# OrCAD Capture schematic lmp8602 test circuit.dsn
size A; title: INA293 40-V High-Voltage, High Bandwidth, Unidirectional, 110-V Common-Mode Current-Sense Amplifier; rev: E1; note: SBOS870
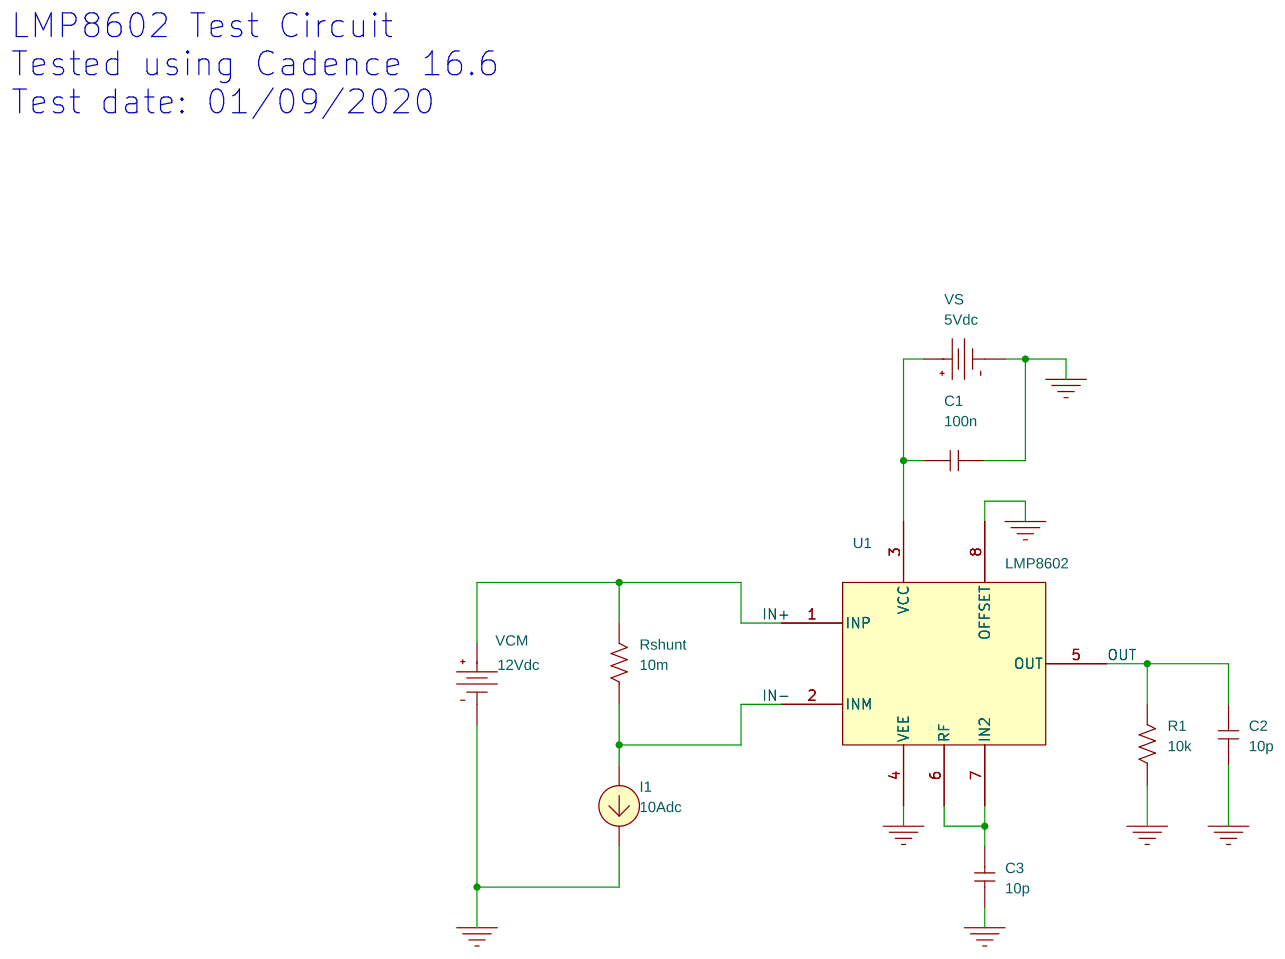
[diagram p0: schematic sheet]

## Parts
C1  100n  [RAD/CK05]
C2  10p  [RAD/CK05]
C3  10p  [RAD/CK05]
I1  IDC
R1  10k  [AX/RC05]
Rshunt  10m  [AX/RC05]
U1  LMP8602
VCM  VDC
VS  VDC

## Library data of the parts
C1-C3 = C
I1 = IDC: DC: 10Adc
R1 Rshunt = R
U1 = LMP8602
VCM = VDC: DC: 12Vdc
VS = VDC: DC: 5Vdc

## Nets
0: C1.1 C2.1 C3.1 I1.2(-) R1.1 U1.4(VEE) U1.8(OFFSET) VCM.1(-) VS.1(-)
IN+: Rshunt.2 U1.1(INP) VCM.0(+)
IN-: I1.1(+) Rshunt.1 U1.2(INM)
OUT: C2.2 R1.2 U1.5(OUT)
N06355: C1.2 U1.3(VCC) VS.0(+)
N19146: C3.2 U1.6(RF) U1.7(IN2)

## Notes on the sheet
- LMP8602 Test Circuit
  Tested using Cadence 16.6
  Test date: 01/09/2020
